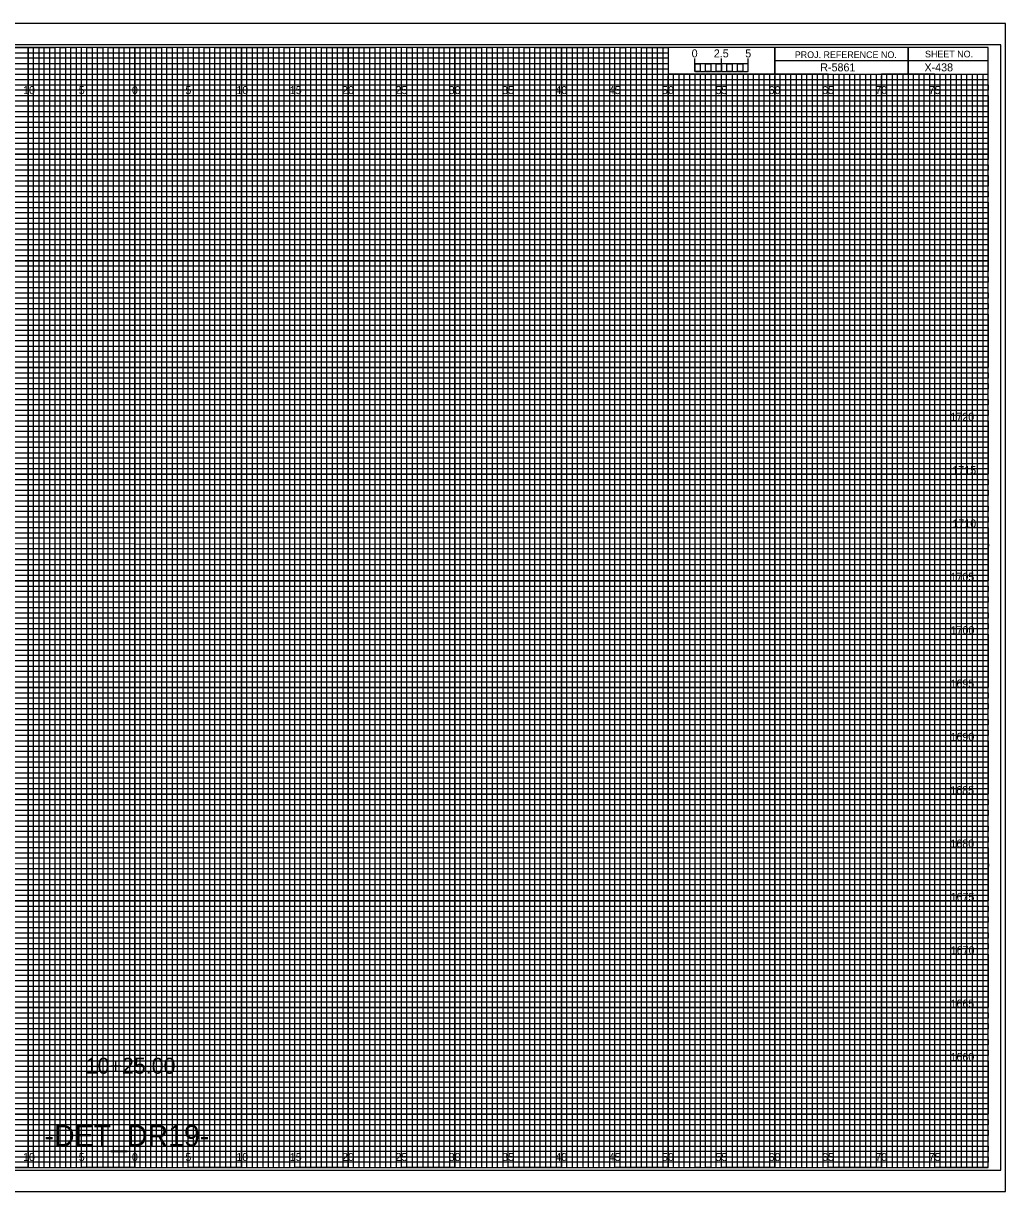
# Model space of a CAD drawing. Extents: x -7 to 162, y -2 to 327.
# Drawn here: x 69.5 to 161.7, y -2.3 to 107.3 of the extents above; entities that cross this region are included whole.
import ezdxf

# ---------------------------------------------------------------- set-up
doc = ezdxf.new("R2010")
doc.units = 0
for name, color, linetype in [('Prop Horizontal Alignment', 7, 'Continuous'), ('Prop XS Alignment Label', 7, 'Continuous'), ('Prop XS Bar Scale Labels', 7, 'Continuous'), ('Prop XS Project Number', 7, 'Continuous'), ('Prop XS Sheet Number', 7, 'Continuous'), ('Raster_Level_0', 7, 'Continuous'), ('Scratch_Level_3', 7, 'Continuous'), ('Sheet Cross Section CELL', 7, 'Continuous'), ('Sheet Cross Section Grid Major CELL', 7, 'Continuous'), ('Sheet Cross Section Grid Middle CELL', 7, 'Continuous'), ('Sheet Cross Section Grid Minor 1 CELL', 7, 'Continuous'), ('Sheet Cross Section Grid Minor 2 CELL', 7, 'Continuous'), ('Sheet Cross Section Scale CELL', 7, 'Continuous'), ('Sheet Cutting Line CELL', 7, 'Continuous'), ('Sheet DOT Grid CELL', 7, 'Continuous'), ('Sheet Plot Border Inside CELL', 7, 'Continuous'), ('Sheet Plot Border Outside CELL', 7, 'Continuous')]:
    doc.layers.add(name, color=color, linetype=linetype)

msp = doc.modelspace()

# ---------------------------------------------------------------- linework, layer by layer
at = {"layer": 'Sheet Cross Section CELL'}
for p, q in [((152.5, 105), (152.5, 102.5)), ((152.5, 102.5), (152.5, 105)), ((160, 103.75), (140, 103.75)), ((140, 103.75), (140, 102.5)), ((140, 102.5), (160, 102.5))]:
    msp.add_line(p, q, dxfattribs=at)
for points in [[(160, 105), (0, 105), (0, 0), (160, 0)], [(140, 105), (130, 105), (130, 102.52), (140, 102.52)], [(160, 105), (140, 105), (140, 102.5), (160, 102.5)]]:
    msp.add_lwpolyline(points, close=True, dxfattribs=at)
at = {"layer": 'Sheet Cross Section Grid Major CELL'}
for p, q in [((75, 105), (70, 105)), ((70, 105), (70, 0)), ((75, 0), (75, 105)), ((85, 105), (80, 105)), ((80, 105), (80, 0)), ((85, 0), (85, 105)), ((95, 105), (90, 105)), ((90, 105), (90, 0)), ((95, 0), (95, 105)), ((105, 105), (100, 105)), ((100, 105), (100, 0)), ((105, 0), (105, 105)), ((115, 105), (110, 105)), ((110, 105), (110, 0)), ((115, 0), (115, 105)), ((125, 105), (120, 105)), ((120, 105), (120, 0)), ((125, 0), (125, 105)), ((130, 105), (130, 0)), ((135, 0), (135, 102.5)), ((145, 102.5), (140, 102.5)), ((140, 102.5), (140, 0)), ((145, 0), (145, 102.5)), ((155, 102.5), (150, 102.5)), ((150, 102.5), (150, 0)), ((155, 0), (155, 102.5)), ((70, 0), (65, 0)), ((80, 0), (75, 0)), ((90, 0), (85, 0)), ((100, 0), (95, 0)), ((110, 0), (105, 0)), ((120, 0), (115, 0)), ((130, 0), (125, 0)), ((140, 0), (135, 0)), ((150, 0), (145, 0)), ((160, 0), (155, 0)), ((160, 0), (160, 0))]:
    msp.add_line(p, q, dxfattribs=at)
for points in [[(0, 100), (160, 100), (160, 95), (0, 95)], [(0, 90), (160, 90), (160, 85), (0, 85)], [(0, 80), (160, 80), (160, 75), (0, 75)], [(0, 70), (160, 70), (160, 65), (0, 65)], [(0, 60), (160, 60), (160, 55), (0, 55)], [(0, 50), (160, 50), (160, 45), (0, 45)], [(0, 40), (160, 40), (160, 35), (0, 35)], [(0, 30), (160, 30), (160, 25), (0, 25)], [(0, 20), (160, 20), (160, 15), (0, 15)], [(0, 10), (160, 10), (160, 5), (0, 5)]]:
    msp.add_lwpolyline(points, dxfattribs=at)
at = {"layer": 'Sheet Cross Section Grid Middle CELL'}
for points in [[(67.5, 105), (72.5, 105), (72.5, 0), (77.5, 0), (77.5, 105), (82.5, 105), (82.5, 0), (87.5, 0), (87.5, 105), (92.5, 105), (92.5, 0), (97.5, 0), (97.5, 105), (102.5, 105), (102.5, 0), (107.5, 0), (107.5, 105), (112.5, 105), (112.5, 0), (117.5, 0), (117.5, 105), (122.5, 105), (122.5, 0), (127.5, 0), (127.5, 105), (129.97, 105), (130, 105), (130, 102.5), (132.5, 102.5), (132.5, 0), (137.5, 0), (137.5, 102.5), (142.5, 102.5), (142.5, 0), (147.5, 0), (147.5, 102.5), (152.5, 102.5), (152.5, 0), (157.5, 0), (157.5, 102.5)], [(0, 102.5), (137.5, 102.5)], [(0, 92.5), (160, 92.5), (160, 97.5), (0, 97.5)], [(0, 82.5), (160, 82.5), (160, 87.5), (0, 87.5)], [(0, 72.5), (160, 72.5), (160, 77.5), (0, 77.5)], [(0, 62.5), (160, 62.5), (160, 67.5), (0, 67.5)], [(0, 52.5), (160, 52.5), (160, 57.5), (0, 57.5)], [(0, 42.5), (160, 42.5), (160, 47.5), (0, 47.5)], [(0, 32.5), (160, 32.5), (160, 37.5), (0, 37.5)], [(0, 22.5), (160, 22.5), (160, 27.5), (0, 27.5)], [(0, 12.5), (160, 12.5), (160, 17.5), (0, 17.5)], [(0, 2.5), (160, 2.5), (160, 7.5), (0, 7.5)]]:
    msp.add_lwpolyline(points, dxfattribs=at)
at = {"layer": 'Sheet Cross Section Grid Minor 1 CELL'}
for p, q in [((0, 104.5), (130, 104.5)), ((130, 104.5), (130, 103.99)), ((130, 103.99), (0, 103.99)), ((0, 103.5), (130, 103.5)), ((130, 102.95), (0, 102.95)), ((130, 103.5), (130, 102.95)), ((0, 102), (160, 102))]:
    msp.add_line(p, q, dxfattribs=at)
for points in [[(0, 101.5), (135, 101.5), (160, 101.5), (160, 101), (0, 101)], [(0, 100.5), (160, 100.5), (160, 99.5), (0, 99.5)], [(0, 99), (160, 99), (160, 98.5), (0, 98.49)], [(0, 98), (160, 98), (160, 97), (0, 97)], [(0, 96.5), (160, 96.5), (160, 96), (0, 96)], [(0, 95.5), (160, 95.5), (160, 94.5), (0, 94.5)], [(0, 94), (160, 94), (160, 93.5), (0, 93.5)], [(0, 93), (160, 93), (160, 92), (0, 92)], [(0, 91.5), (160, 91.5), (160, 91), (0, 91)], [(0, 90.5), (160, 90.5), (160, 89.5), (0, 89.5)], [(0, 89), (160, 89), (160, 88.5), (0, 88.5)], [(0, 88), (160, 88), (160, 86.98), (160, 86.5), (160, 86), (0, 86)], [(0, 87), (160, 87), (160, 86.5), (0, 86.5)], [(0, 85.5), (160, 85.5), (160, 84.5), (0, 84.52)], [(0, 84.52), (160, 84.5), (160, 84), (0, 84)], [(0, 83.5), (160, 83.5), (160, 83), (0, 83)], [(0, 82), (160, 82), (160, 81.5), (0, 81.5)], [(0, 81), (160, 81), (160, 80.5), (0, 80.5)], [(-0.04, 79.45), (160, 79.45), (160, 78.94), (-0.04, 78.94)], [(0, 78.5), (160, 78.5), (160, 78), (0, 78)], [(0, 77), (160, 77), (160, 76.5), (0, 76.5)], [(0, 76), (160, 76), (160, 75.5), (0, 75.5)], [(0, 74.5), (160, 74.5), (160, 74), (0, 74)], [(0, 73.5), (160, 73.5), (160, 73), (0, 73)], [(0, 72), (160, 72), (160, 71.5), (0, 71.5)], [(0, 71), (160, 71), (160, 70.5), (0, 70.5)], [(0, 69.5), (160, 69.5), (160, 68.99), (0, 69)], [(0, 68.5), (160, 68.5), (160, 68), (0, 68)], [(0, 67), (160, 67), (160, 66.5), (0, 66.5)], [(0, 66), (160, 66), (160, 65.5), (0, 65.5)], [(0, 64.5), (160, 64.5), (160, 64), (0, 64)], [(0, 63.5), (160, 63.5), (160, 63), (0, 63)], [(0, 62), (160, 62), (160, 61.5), (0, 61.5)], [(0, 61), (160, 61), (160, 60.5), (0, 60.5)], [(0, 59.5), (160, 59.5), (160, 59), (0, 59)], [(0, 58.5), (160.03, 58.45), (160, 58), (0, 58)], [(0, 57), (160, 57), (160, 56.5), (0, 56.5)], [(0, 56), (160, 56), (160, 55.5), (0, 55.5)], [(0, 54.5), (160, 54.5), (160, 54), (0, 54)], [(0, 53.5), (160, 53.5), (160, 53), (0, 53)], [(0, 52), (160, 52), (160, 51.5), (0, 51.5)], [(0, 51), (160, 51), (160, 50.5), (0, 50.5)], [(0, 49.5), (160, 49.5), (160, 49), (0, 49)], [(0, 48.5), (160, 48.5), (160, 48), (0, 48)], [(0, 47), (160, 47), (160, 46.5), (0, 46.5)], [(0, 46), (160, 46), (160, 45.5), (0, 45.5)], [(0, 44.5), (160, 44.5), (160, 44), (0, 44)], [(0, 43.5), (160, 43.5), (160, 43), (0, 43)], [(0, 42), (160, 42), (160, 41.5), (0, 41.5)], [(0, 41), (160, 41), (160, 40.5), (0, 40.5)], [(0, 39.5), (160, 39.5), (160, 38.99), (0, 39)], [(0, 38.5), (160, 38.5), (160, 38), (0, 38)], [(0, 37), (160, 37), (160, 36.5), (0, 36.5)], [(0, 36), (160, 36), (160, 35.5), (0, 35.5)], [(0, 34.5), (160, 34.5), (160, 34), (0, 34)], [(0, 33.5), (160, 33.5), (160, 33), (0, 33)], [(0, 32), (160, 32), (160, 31.5), (0, 31.5)], [(0, 31), (160, 31), (160, 30.5), (0, 30.5)], [(0, 29.5), (160, 29.5), (160, 29), (0, 29)], [(0, 28.5), (160.03, 28.46), (160, 28), (0, 28)], [(0, 27), (160, 27), (160, 26.5), (0, 26.5)], [(0, 26), (160, 26), (160, 25.5), (0, 25.5)], [(0, 24.5), (160, 24.5), (160, 24), (0, 24)], [(0, 23.5), (160, 23.5), (160, 23), (0, 23)], [(0, 22), (160, 22), (160, 21.5), (0, 21.5)], [(0, 21), (160, 21), (160, 20.5), (0, 20.5)], [(0, 19.5), (160, 19.5), (160, 19), (0, 19)], [(0, 18.5), (160, 18.5), (160, 18), (0, 18)], [(0, 17), (160, 17), (160, 16.5), (0, 16.5)], [(0, 16), (160, 16), (160, 15.5), (0, 15.5)], [(0, 14.5), (160, 14.5), (160, 14), (0, 14)], [(0, 13.5), (160, 13.5), (160, 13), (0, 13)], [(0, 12), (160, 12), (160, 11.5), (0, 11.5)], [(0, 11), (160, 11), (160, 10.5), (0, 10.5)], [(0, 9.5), (160, 9.5), (160, 9), (0, 9)], [(0, 8.5), (160, 8.5), (160, 8), (0, 8)], [(0, 7), (160, 7), (160, 6.5), (0, 6.5)], [(0, 6), (160, 6), (160, 5.5), (0, 5.5)], [(0, 4.5), (160, 4.5), (160, 4), (0, 4)], [(0, 3.5), (160, 3.5), (160, 3), (0, 3)], [(0, 2), (160, 2), (160, 1.5), (0, 1.5)], [(0, 1), (160, 1), (160, 0.5), (0, 0.5)]]:
    msp.add_lwpolyline(points, dxfattribs=at)
at = {"layer": 'Sheet Cross Section Grid Minor 2 CELL'}
for p, q in [((133.5, 102.5), (133, 102.5)), ((133, 102.5), (133, 0)), ((133.5, 0), (133.5, 102.5)), ((134.5, 102.5), (134, 102.5)), ((134, 102.5), (134, 0)), ((134.5, 0), (134.5, 102.5)), ((133, 0), (132.5, 0)), ((134, 0), (133.5, 0))]:
    msp.add_line(p, q, dxfattribs=at)
for points in [[(70, 0), (70.5, 0), (70.5, 105), (71, 105), (71, 0)], [(71, 0), (71.5, 0), (71.5, 105), (72, 105), (72, 0)], [(72.5, 0), (73, 0), (73, 105), (73.5, 105), (73.5, 0)], [(73.5, 0), (74, 0), (74, 105), (74.5, 105), (74.5, 0)], [(75, 0), (75.5, 0), (75.5, 105), (76, 105), (76, 0)], [(76, 0), (76.5, 0), (76.5, 105), (77, 105), (77, 0)], [(77.5, 0), (78, 0), (78, 105), (78.5, 105), (78.5, 0)], [(78.5, 0), (79, 0), (79, 105), (79.5, 105), (79.5, 0)], [(80, 0), (80.5, 0), (80.5, 105), (81, 105), (81, 0)], [(81, 0), (81.5, 0), (81.5, 105), (82, 105), (82, 0)], [(82.5, 0), (83, 0), (83, 105), (83.5, 105), (83.5, 0)], [(83.5, 0), (84, 0), (84, 105), (84.5, 105), (84.5, 0)], [(85, 0), (85.5, 0), (85.5, 105), (86, 105), (86, 0)], [(86, 0), (86.5, 0), (86.5, 105), (87, 105), (87, 0)], [(87.5, 0), (88, 0), (88, 105), (88.5, 105), (88.5, 0)], [(88.5, 0), (89, 0), (89, 105), (89.5, 105), (89.5, 0)], [(90, 0), (90.5, 0), (90.5, 105), (91, 105), (91, 0)], [(91, 0), (91.5, 0), (91.5, 105), (92, 105), (92, 0)], [(92.5, 0), (93, 0), (93, 105), (93.5, 105), (93.5, 0)], [(93.5, 0), (94, 0), (94, 105), (94.5, 105), (94.5, 0)], [(95, 0), (95.5, 0), (95.5, 105), (96, 105), (96, 0)], [(96, 0), (96.5, 0), (96.5, 105), (97, 105), (97, 0)], [(97.5, 0), (98, 0), (98, 105), (98.5, 105), (98.5, 0)], [(98.5, 0), (99, 0), (99, 105), (99.5, 105), (99.5, 0)], [(100, 0), (100.5, 0), (100.5, 105), (101, 105), (101, 0)], [(101, 0), (101.5, 0), (101.5, 105), (102, 105), (102, 0)], [(102.5, 0), (103, 0), (103, 105), (103.5, 105), (103.5, 0)], [(103.5, 0), (104, 0), (104, 105), (104.5, 105), (104.5, 0)], [(105, 0), (105.5, 0), (105.5, 105), (106, 105), (106, 0)], [(106, 0), (106.5, 0), (106.5, 105), (107, 105), (107, 0)], [(107.5, 0), (108, 0), (108, 105), (108.5, 105), (108.5, 0)], [(108.5, 0), (109, 0), (109, 105), (109.5, 105), (109.5, 0)], [(110, 0), (110.5, 0), (110.5, 105), (111, 105), (111, 0)], [(111, 0), (111.5, 0), (111.5, 105), (112, 105), (112, 0)], [(112.5, 0), (113, 0), (113, 105), (113.5, 105), (113.5, 0)], [(113.5, 0), (114, 0), (114, 105), (114.5, 105), (114.5, 0)], [(115, 0), (115.5, 0), (115.5, 105), (116, 105), (116, 0)], [(116, 0), (116.5, 0), (116.5, 105), (117, 105), (117, 0)], [(117.5, 0), (118, 0), (118, 105), (118.5, 105), (118.5, 0)], [(118.5, 0), (119, 0), (119, 105), (119.5, 105), (119.5, 0)], [(120, 0), (120.5, 0), (120.5, 105), (121, 105), (121, 0)], [(121, 0), (121.5, 0), (121.5, 105), (122, 105), (122, 0)], [(122.5, 0), (123, 0), (123, 105), (123.5, 105), (123.5, 0)], [(123.5, 0), (124, 0), (124, 105), (124.5, 105), (124.5, 0)], [(125, 0), (125.5, 0), (125.5, 105), (126, 105), (126, 0)], [(126, 0), (126.5, 0), (126.5, 105), (127, 105), (127, 0)], [(127.5, 0), (128, 0), (128, 105), (128.5, 105), (128.5, 0)], [(128.5, 0), (129, 0), (129, 105), (129.5, 105), (129.5, 0)], [(130, 0), (130.5, 0), (130.5, 102.5), (131.01, 102.5), (131.01, 0)], [(131, 0), (131.5, 0), (131.5, 102.5), (132, 102.5), (132, 0)], [(135, 0), (135.49, 0), (135.49, 102.5), (136, 102.5), (136, 0)], [(136, 0), (136.5, 0), (136.5, 102.5), (137.03, 102.5), (137.03, 0)], [(137.5, 0), (138, 0), (138, 102.5), (138.5, 102.5), (138.5, 0)], [(138.5, 0), (139, 0), (139, 102.5), (139.5, 102.5), (139.5, 0)], [(140, 0), (140.5, 0), (140.5, 102.5), (141, 102.5), (141, 0)], [(141, 0), (141.5, 0), (141.5, 102.5), (142, 102.5), (142, 0)], [(142.5, 0), (143, 0), (143, 102.5), (143.5, 102.5), (143.5, 0)], [(143.5, 0), (144, 0), (144, 102.5), (144.5, 102.5), (144.5, 0)], [(145, 0), (145.5, 0), (145.5, 102.5), (146, 102.5), (146, 0)], [(146, 0), (146.5, 0), (146.5, 102.5), (147, 102.5), (147, 0)], [(147.5, 0), (148, 0), (148, 102.5), (148.5, 102.5), (148.5, 0)], [(148.5, 0), (149, 0), (149, 102.5), (149.5, 102.5), (149.5, 0)], [(150, 0), (150.5, 0), (150.5, 102.5), (151, 102.5), (151, 0)], [(151, 0), (151.5, 0), (151.5, 102.5), (152, 102.5), (152, 0)], [(152.5, 0), (153, 0), (153, 102.5), (153.5, 102.5), (153.5, 0)], [(153.5, 0), (154, 0), (154, 102.5), (154.5, 102.5), (154.5, 0)], [(155, 0), (155.5, 0), (155.5, 102.5), (156, 102.5), (156, 0)], [(156, 0), (156.5, 0), (156.5, 102.5), (157, 102.5), (157, 0)], [(157.5, 0), (158, 0), (158, 102.5), (158.5, 102.5), (158.5, 0)], [(158.5, 0), (159, 0), (159, 102.5), (159.5, 102.5), (159.5, 0)]]:
    msp.add_lwpolyline(points, dxfattribs=at)
at = {"layer": 'Sheet Cross Section Scale CELL'}
for p, q in [((132.5, 102.75), (132.5, 103.95)), ((132.5, 103.45), (132.5, 103.95)), ((135, 102.75), (135, 103.95)), ((137.5, 102.75), (137.5, 103.95)), ((137.5, 103.45), (137.5, 103.95))]:
    msp.add_line(p, q, dxfattribs=at)
for points in [[(137.5, 103.45), (132.5, 103.45), (132.5, 102.75), (137.5, 102.75)], [(132.5, 103.45), (133, 103.45), (133, 102.75), (132.5, 102.75)], [(133.5, 103.45), (134, 103.45), (134, 102.75), (133.5, 102.75)], [(134.5, 103.45), (135, 103.45), (135, 102.75), (134.5, 102.75)], [(135.5, 103.45), (136, 103.45), (136, 102.75), (135.5, 102.75)], [(136.5, 103.45), (137, 103.45), (137, 102.75), (136.5, 102.75)]]:
    msp.add_lwpolyline(points, close=True, dxfattribs=at)
at = {"layer": 'Sheet Cutting Line CELL'}
for p, q in [((161.65, 107.25), (-6.7, 107.25)), ((-6.7, -2.25), (161.65, -2.25))]:
    msp.add_line(p, q, dxfattribs=at)
at = {"layer": 'Sheet DOT Grid CELL'}
for p, q in [((70, 0), (70, 105)), ((75, 0), (75, 105)), ((80, 0), (80, 105)), ((85, 0), (85, 105)), ((90, 0), (90, 105)), ((95, 0), (95, 105)), ((100, 0), (100, 105)), ((105, 0), (105, 105)), ((110, 0), (110, 105)), ((115, 0), (115, 105)), ((120, 0), (120, 105)), ((125, 0), (125, 105)), ((130, 0), (130, 102.34)), ((135, 0), (135, 102.34)), ((140, 0), (140, 102.34)), ((145, 0), (145, 102.34)), ((150, 0), (150, 102.34)), ((155, 0), (155, 102.34)), ((0, 100), (160, 100)), ((0, 95), (160, 95)), ((0, 90), (160, 90)), ((0, 85), (160, 85)), ((0, 80), (160, 80)), ((0, 75), (160, 75)), ((0, 70), (160, 70)), ((0, 65), (160, 65)), ((0, 60), (160, 60)), ((0, 55), (160, 55)), ((0, 50), (160, 50)), ((0, 45), (160, 45)), ((0, 40), (160, 40)), ((0, 35), (160, 35)), ((0, 30), (160, 30)), ((0, 25), (160, 25)), ((0, 20), (160, 20)), ((0, 15), (160, 15)), ((0, 10), (160, 10)), ((0, 5), (160, 5))]:
    msp.add_line(p, q, dxfattribs=at)
at = {"layer": 'Sheet Plot Border Inside CELL'}
msp.add_lwpolyline([(-5.4, -0.25), (161.2, -0.25), (161.2, 105.25), (-5.4, 105.25)], close=True, dxfattribs=at)
at = {"layer": 'Sheet Plot Border Outside CELL'}
msp.add_lwpolyline([(-6.7, -2.25), (161.65, -2.25), (161.65, 107.25), (-6.7, 107.25)], close=True, dxfattribs=at)

# ---------------------------------------------------------------- texts
at = {"layer": 'Prop Horizontal Alignment'}
msp.add_text('10+25.00', height=1.5, dxfattribs=at).set_placement((75.39, 8.8))
at = {"layer": 'Prop XS Alignment Label'}
msp.add_text('-DET_DR19-', height=2, dxfattribs=at).set_placement((71.53, 2))
at = {"layer": 'Prop XS Bar Scale Labels'}
for s, p in [('2.5', (134.29, 104.06)), ('5', (137.24, 104.06))]:
    msp.add_text(s, height=0.75, dxfattribs=at).set_placement(p)
at = {"layer": 'Prop XS Project Number'}
msp.add_text('R-5861', height=0.75, dxfattribs=at).set_placement((144.27, 102.75))
at = {"layer": 'Prop XS Sheet Number'}
msp.add_text('X-438', height=0.75, dxfattribs=at).set_placement((154.04, 102.75))
at = {"layer": 'Raster_Level_0'}
for s, p in [('10', (69.52, 100.62)), ('5', (74.74, 100.62)), ('0', (79.73, 100.62)), ('0', (79.73, 100.62)), ('5', (84.74, 100.62)), ('10', (89.52, 100.62)), ('15', (94.53, 100.62)), ('20', (99.43, 100.62)), ('25', (104.44, 100.62)), ('30', (109.43, 100.62)), ('35', (114.44, 100.62)), ('40', (119.43, 100.62)), ('45', (124.44, 100.62)), ('50', (129.43, 100.62)), ('55', (134.44, 100.62)), ('60', (139.43, 100.62)), ('65', (144.44, 100.62)), ('70', (149.43, 100.62)), ('75', (154.44, 100.62)), ('10', (69.52, 0.62)), ('5', (74.74, 0.62)), ('0', (79.73, 0.62)), ('0', (79.73, 0.62)), ('5', (84.74, 0.62)), ('10', (89.52, 0.62)), ('15', (94.53, 0.62)), ('20', (99.43, 0.62)), ('25', (104.44, 0.62)), ('30', (109.43, 0.62)), ('35', (114.44, 0.62)), ('40', (119.43, 0.62)), ('45', (124.44, 0.62)), ('50', (129.43, 0.62)), ('55', (134.44, 0.62)), ('60', (139.43, 0.62)), ('65', (144.44, 0.62)), ('70', (149.43, 0.62)), ('75', (154.44, 0.62))]:
    msp.add_text(s, height=0.75, dxfattribs=at).set_placement(p)
at = {"layer": 'Scratch_Level_3'}
for s, p in [('1720', (156.47, 70)), ('1715', (156.65, 65)), ('1710', (156.66, 60)), ('1705', (156.48, 55)), ('1700', (156.49, 50)), ('1695', (156.48, 45)), ('1690', (156.48, 40)), ('1685', (156.46, 35)), ('1680', (156.47, 30)), ('1675', (156.49, 25)), ('1670', (156.5, 20)), ('1665', (156.48, 15)), ('1660', (156.48, 10))]:
    msp.add_text(s, height=0.75, dxfattribs=at).set_placement(p)
at = {"layer": 'Sheet Cross Section CELL'}
for s, p in [('PROJ. REFERENCE NO.', (141.88, 104)), ('SHEET NO.', (154.09, 104.06))]:
    msp.add_text(s, height=0.625, dxfattribs=at).set_placement(p)
at = {"layer": 'Sheet Cross Section Scale CELL'}
msp.add_text('0', height=0.75, dxfattribs=at).set_placement((132.21, 104.06))

doc.saveas('drawing.dxf')
